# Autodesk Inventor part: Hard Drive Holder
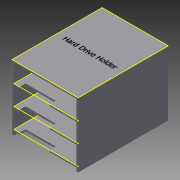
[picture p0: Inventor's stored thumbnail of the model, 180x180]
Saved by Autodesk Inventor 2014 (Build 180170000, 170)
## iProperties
Created: 2013-09
Part Number: Hard Drive Holder
Material: Generic
Document SubType Name: Modeling
Designer: OWNER
Density: 1 g/cm^3
Appearance: Default
Author: OWNER
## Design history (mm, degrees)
sketch "Sketch1"
  geometry: L1 (0, 0)-(110, 0); L2 (110, 0)-(110, 150); L3 (110, 150)-(0, 150); L4 (0, 150)-(0, 0)
  constraints: 8 end point, 2 parallel, 1 horizontal, 1 perpendicular
  dimensions: "d0" = 110 distance of L3.end L2.end; "d1" = 150 distance of L2.end L1.end
extrude "Extrusion1" new body sketch "Sketch1" distance "d2" = 3; taper "d3" = 0 deg
sketch "Sketch2"
  geometry: L1 (0, 0)-(110, 0) reference; L2 (0, 150)-(3, 150); L3 (3, 150)-(3, 0); L4 (3, 0)-(0, 0); L5 (0, 0)-(0, 150); L6 (110, 150)-(107, 150); L7 (107, 150)-(107, 0); L8 (107, 0)-(110, 0); L9 (110, 0)-(110, 150); L10 (3, 150)-(107, 150); L11 (107, 150)-(107, 147); L12 (107, 147)-(3, 147); L13 (3, 147)-(3, 150)
  constraints: 24 end point, 6 parallel, 3 horizontal, 3 perpendicular, 3 point on line
  dimensions: "d4" = 3 distance of L3.end L4.end; "d5" = 3 distance of L8.end L7.end; "d6" = 3 distance of L10.end L11.end
extrude "Extrusion2" join sketch "Sketch2" distance "d7" = 105; taper "d8" = 0 deg
sketch "Sketch3"
  geometry: L1 (104, 0)-(0, 0) reference; L2 (104, 0)-(104, 105) reference; L3 (0, 0)-(0, 105) reference; L4 (0, 30)-(104, 30); L5 (104, 30)-(104, 33); L6 (104, 33)-(0, 33); L7 (0, 33)-(0, 30); L8 (0, 66)-(104, 66); L9 (104, 66)-(104, 63); L10 (104, 63)-(0, 63); L11 (0, 63)-(0, 66); L12 (0, 99)-(104, 99); L13 (104, 99)-(104, 96); L14 (104, 96)-(0, 96); L15 (0, 96)-(0, 99); 1 further point
  constraints: 24 end point, 6 parallel, 6 point on line, 3 horizontal, 3 perpendicular
  dimensions: "d9" = 3 distance of L5.end L4.end; "d10" = 30 distance between parallel lines of L4 L1; "d11" = 3 distance of L8.end L9.end; "d12" = 3 distance of L12.end L13.end; "d13" = 30 distance between parallel lines of L8 L14; "d14" = 30 distance between parallel lines of L10 L6
extrude "Extrusion3" join sketch "Sketch3" distance "d15" = 147; taper "d16" = 0 deg
sketch "Sketch4"
  geometry: L1 (0, 0)-(-110, 0) reference; L2 (0, 150)-(0, 0) reference; L3 (-110, 150)-(0, 150) reference; L4 (-110, 0)-(-110, 150) reference; L5 (-109.19, 150.196)-(0.408, 150.196); L6 (0.408, 150.196)-(0.408, -0.196); L7 (0.408, -0.196)-(-109.19, -0.196); L8 (-109.19, -0.196)-(-109.19, 150.196)
  constraints: 2 other
sketch "Sketch5"
  geometry: L1 (0, 0)-(104, 0) reference; L2 (0, -147)-(0, 0) reference; L3 (104, -147)-(0, -147) reference; L4 (104, 0)-(104, -147) reference; L5 (1.229, -1.673)-(104.811, -1.673); L6 (104.811, -1.673)-(104.811, -150.179); L7 (104.811, -150.179)-(1.229, -150.179); L8 (1.229, -150.179)-(1.229, -1.673); 1 further point
  constraints: 2 other
sketch "Sketch6"
  geometry: L1 (0, 0)-(104, 0) reference; L2 (0, -147)-(0, 0) reference; L3 (104, -147)-(0, -147) reference; L4 (104, 0)-(104, -147) reference; L5 (0.457, 4.989)-(103.294, 4.989); L6 (103.294, 4.989)-(103.294, -143.825); L7 (103.294, -143.825)-(0.457, -143.825); L8 (0.457, -143.825)-(0.457, 4.989); 1 further point
  constraints: 2 other
sketch "Sketch7"
  geometry: L1 (0, 0)-(104, 0) reference; L2 (0, -147)-(0, 0) reference; L3 (104, -147)-(0, -147) reference; L4 (104, 0)-(104, -147) reference; L5 (0.344, -0.111)-(104.626, -0.111); L6 (104.626, -0.111)-(104.626, -148.354); L7 (104.626, -148.354)-(0.344, -148.354); L8 (0.344, -148.354)-(0.344, -0.111); 1 further point
  constraints: 2 other
sketch "Sketch8"
  geometry: L1 (104, -147)-(0, -147) reference; L2 (104, 0)-(104, -147) reference; L3 (94, -147)-(44, -147); L4 (44, -147)-(44, -137); L5 (44, -137)-(94, -137); L6 (94, -137)-(94, -147); 1 further point
  constraints: 8 end point, 2 parallel, 1 horizontal, 1 perpendicular, 1 point on line
  dimensions: "d17" = 50 distance of L4.end L5.end; "d18" = 10 distance of L3.end L4.end; "d19" = 10 distance between parallel lines of L2 L6
extrude "Extrusion4" cut sketch "Sketch8" distance "d20" = 90; taper "d21" = 0 deg
body "Solid1"
